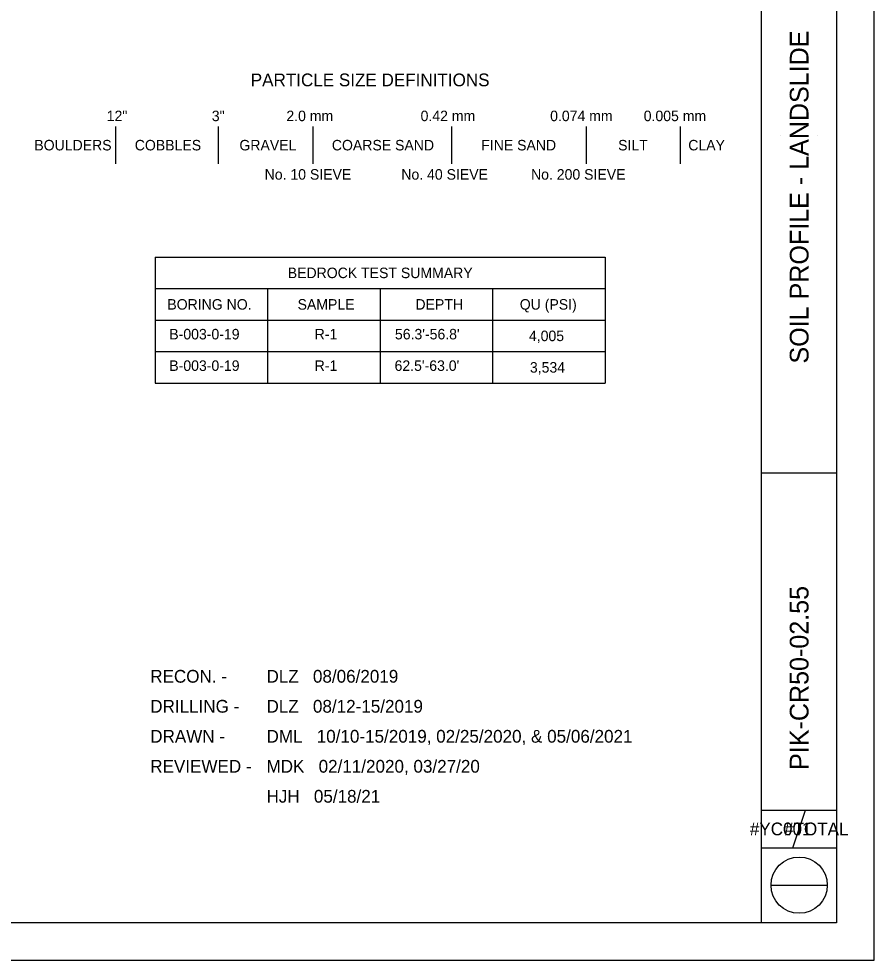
# Model space of a CAD drawing. Extents: x 0 to 34, y 0 to 22.
# Drawn here: x 22.6 to 34, y 0 to 12.55 of the extents above; entities that cross this region are included whole.
import ezdxf

# ---------------------------------------------------------------- set-up
doc = ezdxf.new("R2010")
doc.units = 0
for name, color, linetype in [('SH_Border', 7, 'Continuous'), ('SH_Cut_Line', 7, 'Continuous'), ('SH_Data', 7, 'Continuous'), ('SH_Text', 7, 'Continuous')]:
    doc.layers.add(name, color=color, linetype=linetype)

msp = doc.modelspace()

# ---------------------------------------------------------------- linework, layer by layer
at = {"layer": 'SH_Border'}
for p, q in [((32.5, 0.5), (32.5, 21.5)), ((32.5, 6.5), (33.5, 6.5)), ((32.5, 2), (33.5, 2)), ((32.917, 1.5), (33.083, 2)), ((32.5, 1.5), (33.5, 1.5))]:
    msp.add_line(p, q, dxfattribs=at)
msp.add_lwpolyline([(2, 21.5), (33.5, 21.5), (33.5, 0.5), (2, 0.5)], close=True, dxfattribs=at)
at = {"layer": 'SH_Cut_Line'}
msp.add_lwpolyline([(0, 0), (34, 0), (34, 22), (0, 22)], close=True, dxfattribs=at)
at = {"layer": 'SH_Data'}
for p, q in [((32.75, 11), (32.75, 11)), ((33, 11), (33, 11)), ((33.25, 11), (33.25, 11)), ((24.414, 9.374), (30.414, 9.374)), ((24.414, 9.374), (24.414, 7.694)), ((30.414, 9.374), (30.414, 7.694)), ((24.414, 8.954), (30.414, 8.954)), ((25.914, 8.954), (25.914, 7.694)), ((27.414, 8.954), (27.414, 7.694)), ((28.914, 8.954), (28.914, 7.694)), ((24.414, 8.534), (30.414, 8.534)), ((24.414, 8.114), (30.414, 8.114)), ((24.414, 7.694), (30.414, 7.694)), ((33, 4.25), (33, 4.25)), ((32.625, 1), (33.375, 1))]:
    msp.add_line(p, q, dxfattribs=at)
msp.add_circle((33, 1), 0.375, dxfattribs=at)
at = {"layer": 'SH_Text'}
for p, q in [((23.89, 10.617), (23.89, 11.117)), ((25.26, 10.617), (25.26, 11.117)), ((26.52, 10.617), (26.52, 11.117)), ((28.37, 10.617), (28.37, 11.117)), ((30.165, 10.617), (30.165, 11.117)), ((31.419, 10.617), (31.419, 11.117))]:
    msp.add_line(p, q, dxfattribs=at)

# ---------------------------------------------------------------- texts
at = {"layer": 'SH_Data'}
for s, p in [('SOIL PROFILE - LANDSLIDE', (33.125, 7.955)), ('PIK-CR50-02.55 ', (33.125, 2.537))]:
    msp.add_text(s, height=0.25, rotation=90, dxfattribs=at).set_placement(p)
for s, height, p in [('BEDROCK TEST SUMMARY', 0.14, (26.183, 9.094)), ('BORING NO.', 0.14, (24.578, 8.674)), ('SAMPLE', 0.14, (26.314, 8.674)), ('DEPTH', 0.14, (27.885, 8.674)), ('QU (PSI)', 0.14, (29.276, 8.674)), ('B-003-0-19', 0.14, (24.604, 8.277)), ('R-1', 0.14, (26.542, 8.277)), ("56.3'-56.8'", 0.14, (27.612, 8.277)), ('4,005', 0.14, (29.398, 8.254)), ('B-003-0-19', 0.14, (24.604, 7.857)), ('R-1', 0.14, (26.542, 7.857)), ("62.5'-63.0'", 0.14, (27.607, 7.857)), ('3,534', 0.14, (29.411, 7.834)), ('#YC001', 0.17, (32.343, 1.665)), ('#TOTAL', 0.17, (32.799, 1.665))]:
    msp.add_text(s, height=height, dxfattribs=at).set_placement(p)
at = {"layer": 'SH_Text'}
for s, height, p in [('PARTICLE SIZE DEFINITIONS', 0.17, (25.69, 11.652)), ('12"', 0.14, (23.77, 11.187)), ('3"', 0.14, (25.171, 11.187)), ('2.0 mm', 0.14, (26.165, 11.187)), ('0.42 mm', 0.14, (27.954, 11.187)), ('0.074 mm', 0.14, (29.681, 11.187)), ('0.005 mm', 0.14, (30.928, 11.187)), ('BOULDERS', 0.14, (22.805, 10.797)), ('COBBLES', 0.14, (24.144, 10.797)), ('GRAVEL', 0.14, (25.539, 10.797)), ('COARSE SAND', 0.14, (26.771, 10.797)), ('FINE SAND', 0.14, (28.762, 10.797)), ('SILT', 0.14, (30.587, 10.797)), ('CLAY', 0.14, (31.522, 10.797)), ('No. 10 SIEVE', 0.14, (25.875, 10.407)), ('No. 40 SIEVE', 0.14, (27.697, 10.407)), ('No. 200 SIEVE', 0.14, (29.426, 10.407)), ('RECON. -', 0.17, (24.35, 3.7)), ('DLZ   08/06/2019          ', 0.17, (25.9, 3.7)), ('DRILLING -', 0.17, (24.35, 3.3)), ('DLZ   08/12-15/2019       ', 0.17, (25.9, 3.3)), ('DRAWN -', 0.17, (24.35, 2.9)), ('DML   10/10-15/2019, 02/25/2020, & 05/06/2021      ', 0.17, (25.9, 2.9)), ('REVIEWED -', 0.17, (24.35, 2.5)), ('MDK   02/11/2020, 03/27/20 ', 0.17, (25.9, 2.5)), ('HJH   05/18/21             ', 0.17, (25.9, 2.1))]:
    msp.add_text(s, height=height, dxfattribs=at).set_placement(p)

doc.saveas('drawing.dxf')
